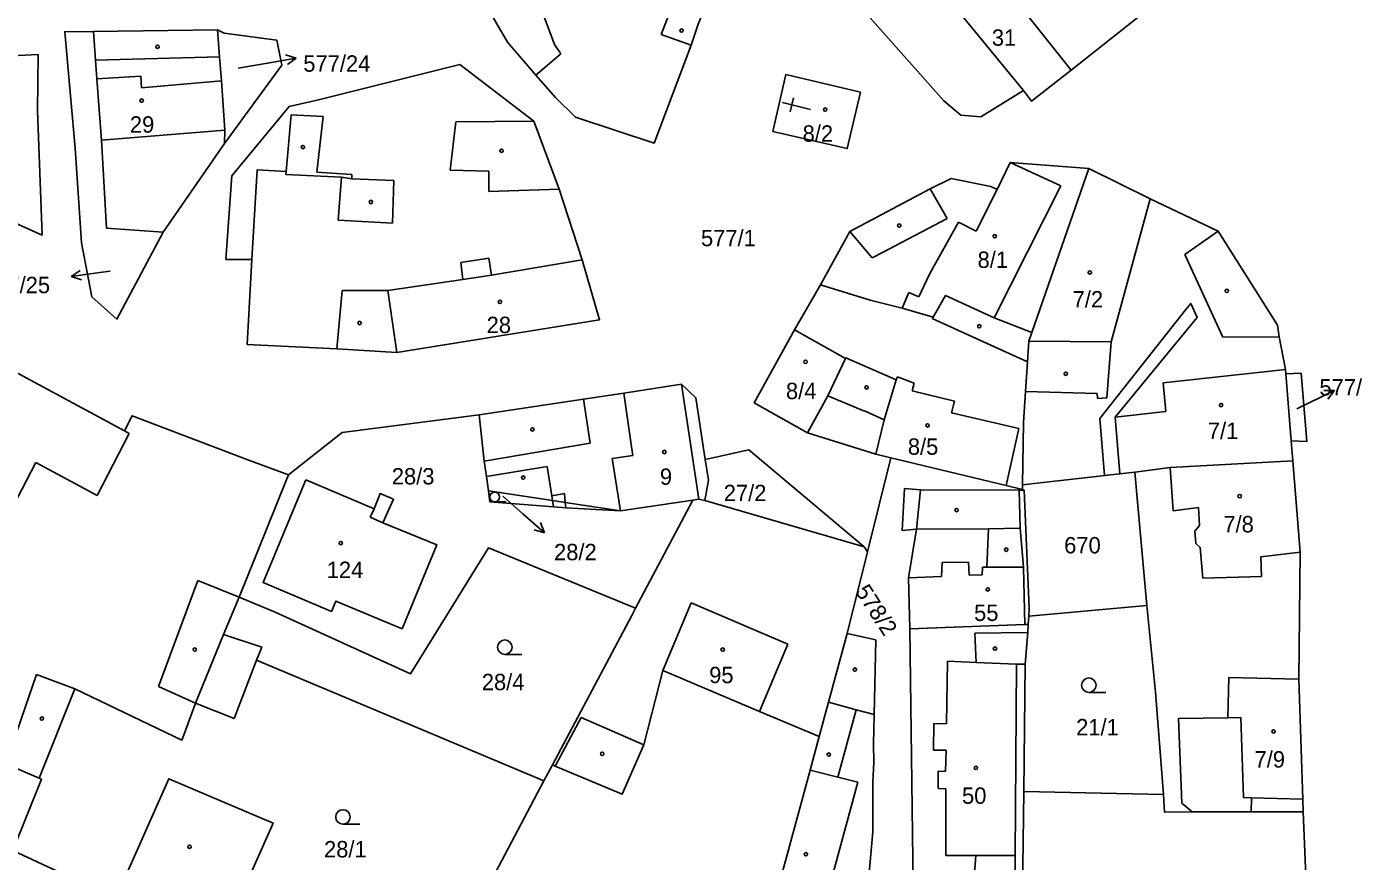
# Model space of a CAD drawing. Extents: x -758582 to -751794, y -998770 to -994350.
# Drawn here: x -754634.2 to -754496.6, y -996913.6 to -996827 of the extents above; entities that cross this region are included whole.
import ezdxf

# ---------------------------------------------------------------- set-up
doc = ezdxf.new("R2010")
doc.units = 0
for name, color, linetype in [('Hranice parcel', 7, 'Continuous'), ('Parcelní čísla', 7, 'Continuous'), ('Pop  PČ popisy', 7, 'Continuous'), ('Vnitřní kresba', 7, 'Continuous'), ('Věcná břemena k části', 7, 'Continuous'), ('Značky budov', 7, 'Continuous'), ('Značky kultur', 7, 'Continuous')]:
    doc.layers.add(name, color=color, linetype=linetype)

msp = doc.modelspace()

# ---------------------------------------------------------------- linework, layer by layer
at = {"layer": 'Hranice parcel'}
for p, q in [((-754627.26, -996827.49), (-754614.39, -996827.33)), ((-754613.67, -996839.12), (-754620.01, -996848.31)), ((-754524.04, -996841.72), (-754529.94, -996858.71)), ((-754524.04, -996841.72), (-754517.66, -996844.85)), ((-754610.81, -996851.14), (-754611.32, -996859.97)), ((-754554.54, -996858.43), (-754551.85, -996853.77)), ((-754529.94, -996858.71), (-754530.27, -996859.6)), ((-754503.65, -996862.56), (-754503.61, -996863.01)), ((-754503.61, -996863.01), (-754503.04, -996869.94)), ((-754503.04, -996869.94), (-754502.87, -996872.02)), ((-754547, -996881.47), (-754544.58, -996871.71)), ((-754544.58, -996871.71), (-754546.11, -996871.34)), ((-754502.87, -996872.02), (-754515.59, -996872.72)), ((-754520.83, -996873.39), (-754530.91, -996874.5)), ((-754519.26, -996873.19), (-754520.83, -996873.39)), ((-754515.59, -996872.72), (-754519.26, -996873.19)), ((-754519.26, -996873.19), (-754518.02, -996887.02)), ((-754586.49, -996873.66), (-754586.3, -996875.13)), ((-754530.91, -996874.5), (-754530.92, -996874.99)), ((-754586.3, -996875.13), (-754586.15, -996876.27)), ((-754572.61, -996877.21), (-754565.1, -996876.12)), ((-754571.03, -996887.31), (-754565.1, -996876.12)), ((-754547.33, -996880.94), (-754563.84, -996876.13)), ((-754530.92, -996874.99), (-754530.92, -996875.06)), ((-754549.09, -996889.92), (-754547, -996881.47)), ((-754547.33, -996880.94), (-754547, -996881.47)), ((-754612.14, -996886.16), (-754613.75, -996890.05)), ((-754612.14, -996886.16), (-754608.4, -996887.74)), ((-754518.02, -996887.02), (-754530.26, -996888.13)), ((-754579.65, -996903.57), (-754571.43, -996888.06)), ((-754571.43, -996888.06), (-754571.03, -996887.31)), ((-754530.26, -996888.13), (-754530.32, -996889)), ((-754530.21, -996887.32), (-754530.26, -996888.13)), ((-754542.6, -996889.47), (-754542.24, -996916.03)), ((-754530.62, -996893.11), (-754530.77, -996906.33)), ((-754502.27, -996894.66), (-754501.84, -996907.12)), ((-754580.53, -996905.22), (-754579.65, -996903.57)), ((-754592.76, -996928.28), (-754580.53, -996905.22)), ((-754530.77, -996906.33), (-754530.91, -996917.89)), ((-754530.77, -996906.33), (-754516.3, -996906.63)), ((-754501.79, -996908.42), (-754501.84, -996907.12)), ((-754500.71, -996936.68), (-754501.79, -996908.42)), ((-754635.62, -996912.43), (-754624.93, -996917.4))]:
    msp.add_line(p, q, dxfattribs=at)
for points in [[(-754537.99, -996797.55), (-754526.76, -996807.06), (-754515.08, -996822.93), (-754525.88, -996831.52)], [(-754525.88, -996831.52), (-754529.97, -996834.72), (-754530.8, -996833.6), (-754535.24, -996836.36), (-754537.32, -996836.16), (-754539.06, -996834.69), (-754550.01, -996822.3), (-754554.77, -996815.29), (-754555.79, -996813.82), (-754556.89, -996808.01), (-754550.29, -996799.98)], [(-754525.88, -996831.52), (-754531.43, -996824.54), (-754535.95, -996819.14), (-754533.11, -996816.66), (-754539.52, -996809.39), (-754535.59, -996806.07), (-754540.94, -996799.81)], [(-754563.13, -996823.1), (-754564.53, -996826.74), (-754565.27, -996828.9), (-754569.1, -996839.07), (-754577.26, -996836.37), (-754579.33, -996834.34), (-754581.37, -996832.02), (-754584.33, -996828.61), (-754587, -996823.94), (-754587.4, -996820.67), (-754586.75, -996817.88), (-754582.85, -996811.54)], [(-754620.01, -996848.31), (-754624.81, -996857.33), (-754627.43, -996855.01), (-754628.48, -996849.41), (-754629.13, -996839.61), (-754630.05, -996829.49), (-754630.23, -996827.53), (-754627.26, -996827.49)], [(-754627.26, -996827.49), (-754627.03, -996830.48), (-754626.89, -996832.42), (-754626.41, -996838.76), (-754625.91, -996847.89), (-754620.01, -996848.31)], [(-754614.39, -996827.33), (-754613.68, -996827.66), (-754608.24, -996828.38), (-754607.71, -996830.98), (-754613.67, -996839.12)], [(-754613.67, -996839.12), (-754613.61, -996837.73), (-754613.97, -996832.61), (-754614.19, -996830.13), (-754614.39, -996827.33)], [(-754640.51, -996830.26), (-754632.97, -996829.89), (-754633.04, -996835.7), (-754632.58, -996848.62), (-754636.71, -996846.74), (-754640.46, -996844.83)], [(-754611.32, -996859.97), (-754602.01, -996860.42), (-754595.8, -996860.79), (-754574.76, -996857.39), (-754576.56, -996851.17), (-754578.95, -996843.84), (-754581.6, -996836.81), (-754589.24, -996830.93), (-754604.06, -996834.62)], [(-754556.8, -996837.87), (-754555.46, -996831.97), (-754547.71, -996833.79), (-754549.08, -996839.64), (-754556.8, -996837.87)], [(-754604.06, -996834.62), (-754606.96, -996835.27), (-754612.91, -996842.46), (-754613.51, -996851.14), (-754610.81, -996851.14)], [(-754551.85, -996853.77), (-754548.83, -996848.23), (-754540.47, -996843.83), (-754538.29, -996842.73), (-754534.2, -996843.59), (-754533.52, -996843.9), (-754532.18, -996841.1), (-754524.04, -996841.72)], [(-754517.66, -996844.85), (-754521.72, -996859.69), (-754530.27, -996859.6)], [(-754517.66, -996844.85), (-754510.61, -996848.2), (-754504.47, -996857.94), (-754504.29, -996859.16), (-754503.65, -996862.56)], [(-754551.85, -996853.77), (-754546.7, -996855.38), (-754543.4, -996856.18), (-754540.19, -996857.11), (-754538.88, -996854.87), (-754533.84, -996857.18), (-754529.94, -996858.71)], [(-754546.11, -996871.34), (-754553.22, -996869.12), (-754558.73, -996866.02), (-754554.54, -996858.43)], [(-754546.11, -996871.34), (-754545.25, -996867.77), (-754544.02, -996863.62), (-754549.23, -996861.35), (-754549.26, -996861.42), (-754554.54, -996858.43)], [(-754530.27, -996859.6), (-754530.4, -996861.76), (-754530.6, -996864.85), (-754530.8, -996868.04), (-754530.91, -996874.5)], [(-754635.97, -996862.48), (-754624.02, -996868.9), (-754623.23, -996867.36), (-754611.24, -996871.93), (-754607.01, -996873.47)], [(-754503.61, -996863.01), (-754502.03, -996862.92), (-754501.41, -996870.01), (-754503.04, -996869.94)], [(-754563.8, -996871.89), (-754564.77, -996865.49), (-754566.26, -996864.08), (-754572.26, -996865.02), (-754576.45, -996865.64), (-754587.24, -996867.25)], [(-754587.24, -996867.25), (-754601.46, -996869.09), (-754607.01, -996873.47)], [(-754587.24, -996867.25), (-754586.75, -996872.05), (-754586.49, -996873.66)], [(-754563.84, -996876.13), (-754563.48, -996874.05), (-754563.8, -996871.89)], [(-754563.8, -996871.89), (-754559.29, -996870.89), (-754547.33, -996880.94)], [(-754544.58, -996871.71), (-754532.61, -996874.58), (-754530.92, -996874.99)], [(-754502.27, -996894.66), (-754502.11, -996881.51), (-754502.87, -996872.02)], [(-754607.01, -996873.47), (-754607.28, -996874.07), (-754612.14, -996886.16)], [(-754605.24, -996874), (-754598.14, -996876.99), (-754597.52, -996875.43), (-754596.15, -996876.02), (-754597.23, -996878.45), (-754591.64, -996880.75), (-754595.25, -996889.44), (-754602.12, -996886.57), (-754602.57, -996887.64), (-754609.66, -996884.64), (-754605.24, -996874)], [(-754586.3, -996875.13), (-754579.64, -996876.14), (-754578.32, -996876.34), (-754572.61, -996877.21)], [(-754565.1, -996876.12), (-754564.49, -996876.01), (-754563.84, -996876.13)], [(-754530.92, -996875.06), (-754531.25, -996875.06), (-754541.47, -996875.05), (-754543.16, -996874.91), (-754543.4, -996879.25), (-754541.91, -996879.12), (-754542.74, -996884.16), (-754542.6, -996889.47)], [(-754530.92, -996875.06), (-754530.74, -996875.06), (-754530.21, -996887.32)], [(-754586.15, -996876.27), (-754579.55, -996876.81), (-754578.26, -996876.9), (-754572.61, -996877.21)], [(-754608.4, -996887.74), (-754594.37, -996894.11), (-754586.29, -996881.06), (-754571.03, -996887.31)], [(-754518.02, -996887.02), (-754517.12, -996896.01), (-754516.3, -996906.63)], [(-754549.09, -996889.92), (-754551.03, -996897.07), (-754551.99, -996900.62)], [(-754549.34, -996932.12), (-754546.88, -996915.56), (-754546.44, -996910.51), (-754546.43, -996905.37), (-754546.32, -996903.3), (-754546.35, -996901.39), (-754546.29, -996898.35), (-754546.13, -996890.6), (-754549.09, -996889.92)], [(-754530.32, -996889), (-754530.67, -996889.01), (-754542.6, -996889.47)], [(-754530.32, -996889), (-754530.37, -996889.83), (-754530.62, -996893.11)], [(-754613.75, -996890.05), (-754616.65, -996897.17), (-754617.81, -996900.29), (-754618.08, -996901), (-754629.17, -996895.68), (-754632.88, -996904.94), (-754632.64, -996905.05), (-754635.62, -996912.43)], [(-754580.53, -996905.22), (-754610.33, -996892.71), (-754609.8, -996891.34), (-754613.75, -996890.05)], [(-754579.65, -996903.57), (-754579.38, -996903.68), (-754572.42, -996906.59), (-754570.19, -996901.47), (-754568.2, -996893.78), (-754558.18, -996898.01), (-754551.99, -996900.62)], [(-754501.84, -996907.12), (-754507.17, -996906.97), (-754508, -996906.95), (-754508.28, -996898.65), (-754509.63, -996898.67), (-754509.52, -996894.51), (-754502.27, -996894.66)], [(-754551.99, -996900.62), (-754552.93, -996904.11), (-754556.98, -996918.99), (-754558.26, -996923.57), (-754559.74, -996928.53)], [(-754613.77, -996921.19), (-754608.62, -996909.6), (-754619.42, -996905), (-754624.93, -996917.4)], [(-754516.3, -996906.63), (-754516.17, -996908.48), (-754513.3, -996908.44)], [(-754513.3, -996908.44), (-754507.19, -996908.43), (-754501.79, -996908.42)]]:
    msp.add_lwpolyline(points, dxfattribs=at)
at = {"layer": 'Pop  PČ popisy'}
for p, q in [((-754612.24, -996831.3), (-754609.2, -996830.77)), ((-754609.2, -996830.77), (-754606.24, -996830.25)), ((-754606.24, -996830.25), (-754607.32, -996829.93)), ((-754606.24, -996830.25), (-754607.14, -996830.92)), ((-754629.55, -996852.92), (-754628.63, -996852.28)), ((-754626.58, -996852.5), (-754629.55, -996852.92)), ((-754625.51, -996852.36), (-754626.58, -996852.5)), ((-754629.55, -996852.92), (-754628.49, -996853.27)), ((-754501.26, -996866.05), (-754498.56, -996864.73)), ((-754498.56, -996864.73), (-754499.68, -996864.72)), ((-754498.56, -996864.73), (-754499.24, -996865.62)), ((-754502.47, -996866.65), (-754501.26, -996866.05)), ((-754584.8, -996875.7), (-754582.74, -996877.51)), ((-754582.74, -996877.51), (-754580.47, -996879.48)), ((-754580.47, -996879.48), (-754580.9, -996878.44)), ((-754580.47, -996879.48), (-754581.56, -996879.2))]:
    msp.add_line(p, q, dxfattribs=at)
at = {"layer": 'Vnitřní kresba'}
for p, q in [((-754540, -996822.41), (-754530.8, -996833.6)), ((-754579.43, -996828.85), (-754580.63, -996825.69)), ((-754567.56, -996825.66), (-754568.38, -996827.8)), ((-754568.38, -996827.8), (-754565.27, -996828.9)), ((-754578.8, -996829.83), (-754579.43, -996828.85)), ((-754627.03, -996830.48), (-754614.19, -996830.13)), ((-754581.37, -996832.02), (-754578.8, -996829.83)), ((-754626.89, -996832.42), (-754622.35, -996832.12)), ((-754622.26, -996833.34), (-754622.35, -996832.12)), ((-754622.26, -996833.34), (-754613.97, -996832.61)), ((-754606.76, -996836.13), (-754607.28, -996842.02)), ((-754603.42, -996836.31), (-754606.76, -996836.13)), ((-754604.07, -996842.1), (-754603.42, -996836.31)), ((-754589.68, -996836.86), (-754590.25, -996841.87)), ((-754581.6, -996836.81), (-754589.68, -996836.86)), ((-754626.41, -996838.76), (-754613.61, -996837.73)), ((-754610.81, -996851.14), (-754610.27, -996841.84)), ((-754607.28, -996842.02), (-754610.27, -996841.84)), ((-754532.18, -996841.1), (-754526.95, -996843.5)), ((-754607.28, -996842.02), (-754607.31, -996842.32)), ((-754607.31, -996842.32), (-754601.53, -996842.6)), ((-754600.45, -996842.33), (-754604.07, -996842.1)), ((-754601.53, -996842.6), (-754601.86, -996847.08)), ((-754600.46, -996842.79), (-754601.53, -996842.6)), ((-754600.46, -996842.79), (-754600.45, -996842.33)), ((-754600.46, -996842.79), (-754596.1, -996842.96)), ((-754596.24, -996847.38), (-754596.1, -996842.96)), ((-754586.25, -996842), (-754590.25, -996841.87)), ((-754586.25, -996842), (-754586.25, -996844.08)), ((-754586.25, -996844.08), (-754578.95, -996843.84)), ((-754538.73, -996846.9), (-754540.47, -996843.83)), ((-754533.52, -996843.9), (-754535.73, -996848.19)), ((-754526.95, -996843.5), (-754533.84, -996857.18)), ((-754596.24, -996847.38), (-754601.86, -996847.08)), ((-754545.43, -996850.42), (-754538.73, -996846.9)), ((-754540.54, -996852.68), (-754537.55, -996847.27)), ((-754535.73, -996848.19), (-754537.55, -996847.27)), ((-754546.5, -996850.98), (-754548.83, -996848.23)), ((-754510.61, -996848.2), (-754514.07, -996850.64)), ((-754586.25, -996851.02), (-754589.14, -996851.45)), ((-754588.95, -996853.22), (-754589.14, -996851.45)), ((-754586.25, -996851.02), (-754585.99, -996852.78)), ((-754576.56, -996851.17), (-754585.99, -996852.78)), ((-754545.43, -996850.42), (-754546.5, -996850.98)), ((-754514.07, -996850.64), (-754510.13, -996859.21)), ((-754588.95, -996853.22), (-754585.99, -996852.78)), ((-754541.67, -996855.03), (-754540.54, -996852.68)), ((-754588.95, -996853.22), (-754596.73, -996854.36)), ((-754602.01, -996860.42), (-754601.47, -996854.36)), ((-754596.73, -996854.36), (-754601.47, -996854.36)), ((-754596.73, -996854.36), (-754595.8, -996860.79)), ((-754542.69, -996854.58), (-754543.4, -996856.18)), ((-754542.69, -996854.58), (-754541.67, -996855.03)), ((-754540.29, -996857.27), (-754540.19, -996857.11)), ((-754540.29, -996857.27), (-754530.4, -996861.76)), ((-754521.72, -996859.69), (-754522.18, -996865.49)), ((-754510.13, -996859.21), (-754504.29, -996859.16)), ((-754551.08, -996865.27), (-754549.26, -996861.42)), ((-754543.86, -996863.32), (-754544.02, -996863.62)), ((-754543.86, -996863.32), (-754542.14, -996863.98)), ((-754516.34, -996863.94), (-754503.65, -996862.56)), ((-754572.26, -996865.02), (-754571.46, -996870.57)), ((-754566.26, -996864.08), (-754564.49, -996876.01)), ((-754542.34, -996864.78), (-754542.14, -996863.98)), ((-754537.97, -996865.83), (-754542.34, -996864.78)), ((-754523.17, -996865.06), (-754530.6, -996864.85)), ((-754523.17, -996865.06), (-754523.15, -996865.57)), ((-754516.34, -996863.94), (-754516.03, -996866.9)), ((-754575.75, -996870.18), (-754576.45, -996865.64)), ((-754553.22, -996869.12), (-754551.08, -996865.27)), ((-754547.31, -996866.89), (-754551.08, -996865.27)), ((-754538.26, -996867.05), (-754537.97, -996865.83)), ((-754522.18, -996865.49), (-754523.15, -996865.57)), ((-754547.28, -996866.85), (-754547.31, -996866.89)), ((-754545.25, -996867.77), (-754547.28, -996866.85)), ((-754531.29, -996868.69), (-754538.26, -996867.05)), ((-754521.29, -996867.5), (-754516.03, -996866.9)), ((-754520.83, -996873.39), (-754521.29, -996867.5)), ((-754623.54, -996869.18), (-754626.86, -996875.61)), ((-754623.54, -996869.18), (-754624.02, -996868.9)), ((-754531.29, -996868.69), (-754532.61, -996874.58)), ((-754586.75, -996872.05), (-754575.75, -996870.18)), ((-754571.32, -996871.47), (-754571.46, -996870.57)), ((-754573.45, -996871.78), (-754571.32, -996871.47)), ((-754572.61, -996877.21), (-754573.45, -996871.78)), ((-754633.22, -996872.21), (-754637.13, -996879.67)), ((-754626.86, -996875.61), (-754633.22, -996872.21)), ((-754586.49, -996873.66), (-754580.2, -996872.63)), ((-754580.2, -996872.63), (-754579.7, -996875.66)), ((-754515.27, -996877.2), (-754515.59, -996872.72)), ((-754579.7, -996875.66), (-754578.41, -996875.43)), ((-754579.7, -996875.66), (-754579.64, -996876.14)), ((-754579.64, -996876.14), (-754579.55, -996876.81)), ((-754578.41, -996875.43), (-754578.32, -996876.34)), ((-754541.91, -996879.12), (-754541.47, -996875.05)), ((-754531.14, -996879.01), (-754531.25, -996875.06)), ((-754598.14, -996876.99), (-754598.54, -996877.86)), ((-754578.32, -996876.34), (-754578.26, -996876.9)), ((-754512.66, -996876.87), (-754515.27, -996877.2)), ((-754512.57, -996878.72), (-754512.66, -996876.87)), ((-754598.54, -996877.86), (-754597.23, -996878.45)), ((-754512.57, -996878.72), (-754513.04, -996879.32)), ((-754541.91, -996879.12), (-754534.44, -996879.08)), ((-754534.6, -996883.06), (-754534.44, -996879.08)), ((-754534.44, -996879.08), (-754531.14, -996879.01)), ((-754530.8, -996883.05), (-754531.14, -996879.01)), ((-754513.04, -996879.32), (-754512.94, -996880.59)), ((-754512.94, -996880.59), (-754512.5, -996881.01)), ((-754512.21, -996884.21), (-754512.5, -996881.01)), ((-754506.19, -996882), (-754502.11, -996881.51)), ((-754539.25, -996882.59), (-754539.3, -996884.01)), ((-754536.5, -996882.55), (-754539.25, -996882.59)), ((-754536.44, -996883.9), (-754536.5, -996882.55)), ((-754535.07, -996883.06), (-754535.08, -996883.84)), ((-754534.6, -996883.06), (-754535.07, -996883.06)), ((-754534.6, -996883.06), (-754530.8, -996883.05)), ((-754530.67, -996889.01), (-754530.8, -996883.05)), ((-754506.13, -996884.03), (-754506.19, -996882)), ((-754616.44, -996884.44), (-754620.52, -996895.45)), ((-754616.44, -996884.44), (-754612.14, -996886.16)), ((-754542.74, -996884.16), (-754539.3, -996884.01)), ((-754536.44, -996883.9), (-754535.08, -996883.84)), ((-754512.21, -996884.21), (-754506.13, -996884.03)), ((-754568.2, -996893.78), (-754565.26, -996886.76)), ((-754565.26, -996886.76), (-754555.24, -996891.04)), ((-754535.85, -996889.89), (-754530.37, -996889.83)), ((-754535.71, -996892.93), (-754535.85, -996889.89)), ((-754555.24, -996891.04), (-754558.18, -996898.01)), ((-754612.65, -996898.76), (-754610.33, -996892.71)), ((-754538.69, -996892.81), (-754538.79, -996899.3)), ((-754535.71, -996892.93), (-754538.69, -996892.81)), ((-754531.53, -996893.11), (-754535.71, -996892.93)), ((-754531.67, -996912.96), (-754531.53, -996893.11)), ((-754530.62, -996893.11), (-754531.53, -996893.11)), ((-754633.14, -996894.2), (-754636.35, -996903.45)), ((-754629.17, -996895.68), (-754633.14, -996894.2)), ((-754620.52, -996895.45), (-754616.65, -996897.17)), ((-754616.65, -996897.17), (-754612.65, -996898.76)), ((-754551.03, -996897.07), (-754548.15, -996897.85)), ((-754548.15, -996897.85), (-754550.05, -996904.84)), ((-754548.15, -996897.85), (-754546.29, -996898.35)), ((-754576.68, -996898.65), (-754579.38, -996903.68)), ((-754576.68, -996898.65), (-754570.19, -996901.47)), ((-754540.15, -996902.05), (-754540.1, -996899.26)), ((-754540.1, -996899.26), (-754538.79, -996899.3)), ((-754514.75, -996898.75), (-754509.63, -996898.67)), ((-754514.4, -996907.53), (-754514.75, -996898.75)), ((-754538.81, -996902.05), (-754540.15, -996902.05)), ((-754538.81, -996902.05), (-754538.88, -996904.24)), ((-754636.35, -996903.45), (-754632.88, -996904.94)), ((-754550.05, -996904.84), (-754552.93, -996904.11)), ((-754550.05, -996904.84), (-754547.97, -996905.36)), ((-754539.67, -996906.03), (-754539.66, -996904.23)), ((-754539.66, -996904.23), (-754538.88, -996904.24)), ((-754547.97, -996905.36), (-754552.05, -996920.32)), ((-754539.67, -996906.03), (-754538.86, -996906.06)), ((-754538.86, -996906.06), (-754538.87, -996912.95)), ((-754513.3, -996908.44), (-754514.4, -996907.53)), ((-754507.17, -996906.97), (-754507.19, -996908.43)), ((-754538.87, -996912.95), (-754535.74, -996912.95)), ((-754536.06, -996917.05), (-754535.74, -996912.95)), ((-754535.74, -996912.95), (-754531.67, -996912.96)), ((-754531.71, -996917.76), (-754531.67, -996912.96))]:
    msp.add_line(p, q, dxfattribs=at)
at = {"layer": 'Věcná břemena k části'}
msp.add_lwpolyline([(-754522.41, -996873.56), (-754520.83, -996873.39), (-754521.29, -996867.5), (-754513.31, -996857.79), (-754512.8, -996857.17), (-754513.47, -996855.7), (-754513.97, -996856.33), (-754522.88, -996867.62)], close=True, dxfattribs=at)
at = {"layer": 'Značky budov'}
for p, q in [((-754555.8, -996834.87), (-754552.89, -996835.6)), ((-754555.01, -996835.84), (-754554.65, -996834.39))]:
    msp.add_line(p, q, dxfattribs=at)
for centre in [(-754566.26, -996827.4), (-754620.61, -996829.08), (-754622.25, -996834.66), (-754551.36, -996835.6), (-754605.53, -996839.49), (-754584.93, -996839.86), (-754598.48, -996845.18), (-754543.69, -996847.63), (-754533.79, -996848.73), (-754523.93, -996852.49), (-754509.72, -996854.41), (-754585.1, -996855.54), (-754599.65, -996857.73), (-754535.39, -996858.07), (-754553.41, -996861.76), (-754526.43, -996862.99), (-754547.08, -996864.41), (-754510.32, -996866.25), (-754581.73, -996868.77), (-754540.75, -996868.36), (-754568.05, -996871.11), (-754582.68, -996873.76), (-754508.39, -996875.69), (-754537.75, -996877.13), (-754601.61, -996880.56), (-754532.6, -996881.24), (-754534.51, -996885.36), (-754533.76, -996891.5), (-754616.74, -996891.61), (-754562, -996891.61), (-754548.29, -996893.68), (-754632.59, -996898.76), (-754504.87, -996900.09), (-754574.49, -996902.42), (-754551, -996902.49), (-754535.74, -996903.88), (-754617.29, -996912.05), (-754553.37, -996912.83)]:
    msp.add_circle(centre, 0.175, dxfattribs=at)
at = {"layer": 'Značky kultur'}
for p, q in [((-754585.65, -996876.27), (-754584.47, -996876.27)), ((-754584.59, -996892.11), (-754582.84, -996892.11)), ((-754524.03, -996896.05), (-754522.28, -996896.05)), ((-754601.38, -996909.71), (-754599.63, -996909.71))]:
    msp.add_line(p, q, dxfattribs=at)
for centre, radius in [((-754585.65, -996875.77), 0.502), ((-754584.59, -996891.36), 0.75), ((-754524.03, -996895.3), 0.75), ((-754601.38, -996908.96), 0.75)]:
    msp.add_circle(centre, radius, dxfattribs=at)

# ---------------------------------------------------------------- texts
at = {"layer": 'Parcelní čísla'}
for s, p in [('31', (-754534.09, -996828.98)), ('577/24', (-754605.49, -996831.67)), ('29', (-754623.47, -996837.99)), ('8/2', (-754553.71, -996838.93)), ('577/1', (-754564.25, -996849.77)), ('8/1', (-754535.57, -996852.02)), ('577/25', (-754638.7, -996854.64)), ('7/2', (-754525.71, -996856.12)), ('28', (-754586.48, -996858.78)), ('8/4', (-754555.44, -996865.63)), ('577/21', (-754500.12, -996865.25)), ('7/1', (-754511.69, -996869.76)), ('8/5', (-754542.8, -996871.4)), ('28/3', (-754596.31, -996874.48)), ('9', (-754568.51, -996874.52)), ('27/2', (-754561.89, -996876.21)), ('7/8', (-754510.08, -996879.45)), ('670', (-754526.59, -996881.63)), ('28/2', (-754579.49, -996882.34)), ('124', (-754603.06, -996884.18)), ('55', (-754535.93, -996888.64)), ('28/4', (-754586.98, -996895.82)), ('95', (-754563.4, -996895.09)), ('21/1', (-754525.35, -996900.5)), ('7/9', (-754506.85, -996903.84)), ('50', (-754537.18, -996907.6)), ('28/1', (-754603.34, -996913.16))]:
    msp.add_text(s, height=1.7, dxfattribs=at).set_placement(p)
msp.add_text('578/2', height=1.7, rotation=303, dxfattribs=at).set_placement((-754548.32, -996885.56))

doc.saveas('drawing.dxf')
